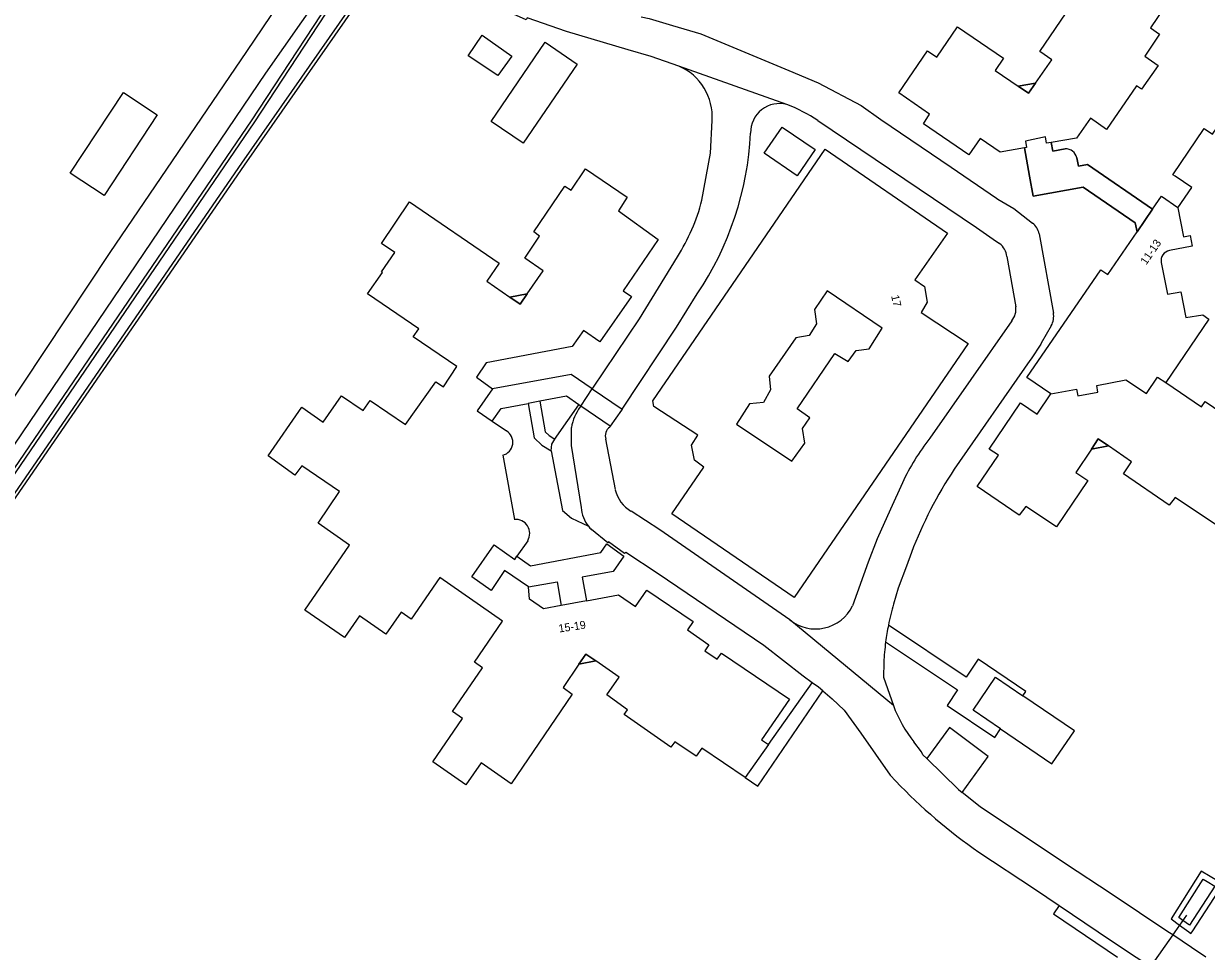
# Model space of a CAD drawing. Extents: x 158132 to 159658, y 385257 to 387209.
# Drawn here: x 159219.1 to 159366.9, y 385997.6 to 386113.4 of the extents above; entities that cross this region are included whole.
import ezdxf

# ---------------------------------------------------------------- set-up
doc = ezdxf.new("R2010")
doc.units = 0
for name, color, linetype in [('IMGEO_Duiker', 7, 'Continuous'), ('IMGEO_Groenvoorziening', 7, 'Continuous'), ('IMGEO_Pand', 7, 'Continuous'), ('IMGEO_Pand_nummerreeks', 7, 'Continuous'), ('IMGEO_Pand_overbouw', 7, 'Continuous'), ('IMGEO_Parkeervlak_open', 7, 'Continuous'), ('IMGEO_Rijbaan_lokaal_gesloten', 7, 'Continuous'), ('IMGEO_Voetpad_open', 7, 'Continuous'), ('IMGEO_Waterloop', 7, 'Continuous')]:
    doc.layers.add(name, color=color, linetype=linetype)

msp = doc.modelspace()

# ---------------------------------------------------------------- linework, layer by layer
at = {"layer": 'IMGEO_Duiker'}
msp.add_lwpolyline([(159364.38, 386002.06), (159363.53, 386000.84), (159362.95, 386000), (159362.67, 385999.6), (159359.91, 385995.65), (159358.31, 385993.36), (159357.26, 385991.85)], dxfattribs=at)
at = {"layer": 'IMGEO_Groenvoorziening'}
for points in [[(159211.05, 386044.02), (159246.68, 386095.71), (159262.72, 386118.74), (159262.51, 386120.37), (159261.9, 386120.78), (159261.17, 386121.26), (159260.05, 386120.35), (159247.53, 386101.26), (159209.27, 386045.25)], [(159343.38, 386105.59), (159345.53, 386105.96)], [(159358.22, 386087.41), (159357.99, 386088.53), (159351.47, 386092.96), (159345.24, 386091.86), (159344.79, 386094.36), (159344.16, 386097.89)], [(159347.5, 386098.55), (159347.68, 386097.45), (159349.25, 386097.78)], [(159350.69, 386096.64), (159350.88, 386095.61), (159352.04, 386095.79), (159360.15, 386090.24)], [(159279.83, 386079.26), (159282.02, 386079.67)], [(159354.64, 386060.67), (159352.51, 386060.27)], [(159290.58, 386033.81), (159288.48, 386033.4)], [(159368.96, 386005.93), (159367.34, 386006.89), (159366.22, 386007.55), (159362.48, 386001.6), (159363.53, 386000.84), (159364.68, 386000), (159364.95, 385999.8), (159365.08, 386000), (159368.96, 386005.93)]]:
    msp.add_lwpolyline(points, dxfattribs=at)
msp.add_arc((159349.27, 386096.33), 1.44, 12.0964, 91.081, dxfattribs=at)
at = {"layer": 'IMGEO_Pand'}
for points in [[(159345.53, 386105.96), (159347.56, 386108.88), (159346.06, 386109.9), (159349.99, 386115.64), (159350.99, 386114.96), (159355.38, 386121.31), (159358.06, 386119.48), (159358.15, 386119.59), (159359.43, 386118.64), (159359.56, 386118.8), (159362.52, 386116.78), (159359.88, 386112.88), (159361, 386112.06), (159359.19, 386109.35), (159360.84, 386108.18), (159358.78, 386105.2), (159358.15, 386105.62), (159354.39, 386100.18), (159352.38, 386101.59), (159350.66, 386099.08), (159347.5, 386098.55)], [(159344.16, 386097.89), (159341.12, 386097.34), (159338.63, 386099.05), (159337.2, 386097.02), (159331.52, 386100.9), (159332.29, 386102.07), (159328.43, 386104.75), (159332.03, 386109.98), (159333.19, 386109.21), (159335.8, 386113.01), (159341.54, 386109.07), (159340.47, 386107.55), (159343.38, 386105.59)], [(159278.36, 386106.9), (159274.62, 386109.39), (159276.38, 386111.95), (159280.1, 386109.33), (159278.36, 386106.9)], [(159277.51, 386101.19), (159284.25, 386111.07), (159288.26, 386108.34), (159281.52, 386098.46), (159277.51, 386101.19)], [(159345.53, 386105.96), (159344.67, 386104.72), (159343.38, 386105.59)], [(159363.33, 386090.38), (159365.05, 386092.93), (159362.96, 386094.34), (159362.7, 386094.52), (159366.6, 386100.31), (159367.66, 386099.59), (159371.3, 386104.98), (159375.09, 386102.42), (159375.76, 386103.43), (159376.87, 386102.67), (159378.1, 386104.47), (159381.25, 386102.35), (159377.56, 386096.85), (159378.57, 386096.17), (159374.68, 386090.38), (159373.18, 386091.39), (159371.26, 386088.52)], [(159231.56, 386104.78), (159235.78, 386101.99), (159229.16, 386091.95), (159224.93, 386094.74), (159231.56, 386104.78)], [(159311.64, 386097.21), (159313.88, 386100.48), (159317.99, 386097.66), (159315.76, 386094.39), (159311.64, 386097.21)], [(159347.5, 386098.55), (159346.9, 386098.45), (159346.76, 386099.24), (159344.29, 386098.71), (159344.42, 386097.94), (159344.16, 386097.89)], [(159304.07, 386058.01), (159302.92, 386058.89), (159302.53, 386060.76), (159303.35, 386062.02), (159297.85, 386065.6), (159297.72, 386066.29), (159319.25, 386097.72), (159334.52, 386087.24), (159330.43, 386081.4), (159331.64, 386080.57), (159332.01, 386078.61), (159331.22, 386077.34), (159337.1, 386073.46), (159315.37, 386041.72), (159300.08, 386052.17), (159304.07, 386058.01)], [(159282.02, 386079.67), (159283.99, 386082.54), (159281.73, 386084.09), (159283.56, 386086.86), (159282.83, 386087.4), (159286.72, 386093.11), (159287.51, 386092.58), (159289.32, 386095.28), (159294.51, 386091.71), (159293.41, 386090.03), (159298.38, 386086.42), (159294.02, 386080.05), (159295.04, 386079.34), (159291.09, 386073.68), (159289.05, 386075.07), (159287.64, 386073.08), (159276.87, 386071.04), (159275.67, 386069.23), (159277.67, 386067.81)], [(159360.15, 386090.24), (159361.26, 386091.86), (159363.32, 386090.45), (159363.33, 386090.38)], [(159288.48, 386033.4), (159286.49, 386030.49), (159287.63, 386029.66), (159280.03, 386018.47), (159276.27, 386021.08), (159274.35, 386018.34), (159270.24, 386021.21), (159273.95, 386026.65), (159272.7, 386027.51), (159276.43, 386032.95), (159275.41, 386033.66), (159278.92, 386038.79), (159271.08, 386044.23), (159267.53, 386039.05), (159266.25, 386039.9), (159264.34, 386037.17), (159261.06, 386039.43), (159259.19, 386036.73), (159254.23, 386040.15), (159259.83, 386048.27), (159255.89, 386051.04), (159258.56, 386054.96), (159253.85, 386058.19), (159253, 386057.03), (159249.67, 386059.42), (159253.84, 386065.52), (159256.54, 386063.64), (159258.81, 386066.94), (159261.51, 386065.09), (159262.39, 386066.32), (159266.82, 386063.33), (159270.59, 386068.68), (159271.54, 386068.04), (159273.23, 386070.6), (159267.78, 386074.27), (159268.46, 386075.27), (159262.08, 386079.66), (159263.93, 386082.3), (159263.83, 386082.4), (159265.46, 386084.81), (159263.79, 386085.92), (159267.32, 386091.16), (159278.51, 386083.48), (159276.96, 386081.24), (159279.83, 386079.26)], [(159360.15, 386090.24), (159358.22, 386087.41)], [(159363.33, 386090.38), (159364.03, 386086.77), (159364.83, 386086.93), (159365.08, 386085.59), (159362.26, 386085.06)], [(159347.45, 386067.15), (159344.46, 386069.2), (159353.67, 386082.67), (159354.56, 386082.06), (159358.22, 386087.41)], [(159361.24, 386083.56), (159362, 386079.6), (159363.67, 386079.92), (159364.3, 386076.69), (159366.42, 386077.03), (159367.19, 386076.5)], [(159319.51, 386080.03), (159317.92, 386077.68), (159318.15, 386075.9), (159317.24, 386074.44), (159315.56, 386074.17), (159312.23, 386069.39), (159312.42, 386067.65), (159311.55, 386066.1), (159309.77, 386065.9), (159308.16, 386063.39), (159315.06, 386058.75), (159316.71, 386061.02), (159316.42, 386062.85), (159317.32, 386064.16), (159315.75, 386065.3), (159320.46, 386072.2), (159322.13, 386071.19), (159323.13, 386072.6), (159324.73, 386072.79), (159326.38, 386075.35), (159319.51, 386080.03)], [(159282.02, 386079.67), (159281.13, 386078.37), (159279.83, 386079.26)], [(159367.19, 386076.5), (159361.79, 386068.57)], [(159347.45, 386067.15), (159350.65, 386067.76), (159350.82, 386066.93), (159353.33, 386067.39), (159353.17, 386068.21), (159356.81, 386068.93), (159359.38, 386067.23), (159360.76, 386069.27), (159361.79, 386068.57)], [(159361.79, 386068.57), (159366.27, 386065.55), (159366.71, 386066.22), (159369.72, 386064.16), (159368.6, 386062.46), (159371.29, 386060.57), (159370.51, 386059.44), (159374.35, 386056.76), (159372.36, 386053.78), (159372.22, 386053.88), (159371.28, 386052.58), (159371.17, 386052.65), (159369.38, 386049.95), (159362.99, 386054.24), (159362.24, 386053.27), (159356.52, 386057.16), (159357.54, 386058.69), (159354.64, 386060.67)], [(159277.67, 386067.81), (159275.78, 386065.03), (159277.63, 386063.76)], [(159352.51, 386060.27), (159350.55, 386057.34), (159352.05, 386056.33), (159348.13, 386050.57), (159344.31, 386053.12), (159343.5, 386052), (159338.23, 386055.58), (159340.9, 386059.52), (159339.73, 386060.28), (159343.67, 386066.03), (159345.73, 386064.62), (159347.45, 386067.15)], [(159277.63, 386063.76), (159279.42, 386062.54)], [(159352.51, 386060.27), (159353.37, 386061.54), (159354.64, 386060.67)], [(159278.96, 386059.5), (159280.41, 386051.49)], [(159282.08, 386048.83), (159280.74, 386046.88)], [(159282.16, 386043.08), (159279.19, 386045.1), (159277.51, 386042.61), (159275.11, 386044.3), (159277.89, 386048.33), (159280.47, 386046.49), (159280.74, 386046.88)], [(159286.27, 386040.73), (159284.07, 386040.32), (159282.32, 386041.52), (159282.16, 386043.08)], [(159289.43, 386041.33), (159286.27, 386040.73)], [(159289.43, 386041.33), (159293.44, 386042.08), (159295.55, 386040.63), (159296.96, 386042.66), (159302.74, 386038.75), (159302.05, 386037.7), (159304.73, 386035.83), (159304.21, 386035.09), (159305.76, 386034.03), (159306.3, 386034.79), (159314.77, 386029.04), (159311.3, 386023.98), (159312.18, 386023.39)], [(159288.48, 386033.4), (159289.35, 386034.67), (159290.58, 386033.81)], [(159309.25, 386019.25), (159303.84, 386022.94), (159303.11, 386021.91), (159300.48, 386023.72), (159299.98, 386023.05), (159294.11, 386027.11), (159294.56, 386027.73), (159291.98, 386029.58), (159293.49, 386031.79), (159290.58, 386033.81)], [(159341.17, 386025.33), (159337.72, 386027.68), (159340.54, 386031.8), (159343.95, 386029.47)], [(159341.17, 386025.33), (159347.58, 386020.96), (159350.4, 386025.07), (159343.95, 386029.47)], [(159312.18, 386023.39), (159309.25, 386019.25)]]:
    msp.add_lwpolyline(points, dxfattribs=at)
for centre, radius, start, end in [((159362.48, 386083.82), 1.26, 100.2132, 191.7914), ((159278.55, 386061.12), 1.67, 284.0563, 58.6242), ((159280.56, 386049.73), 1.77, 329.3209, 95.1105)]:
    msp.add_arc(centre, radius, start, end, dxfattribs=at)
at = {"layer": 'IMGEO_Pand_overbouw'}
for points in [[(159345.53, 386105.96), (159343.38, 386105.59), (159344.67, 386104.72)], [(159279.83, 386079.26), (159281.13, 386078.37), (159282.02, 386079.67)], [(159352.51, 386060.27), (159354.64, 386060.67), (159353.37, 386061.54)], [(159288.48, 386033.4), (159290.58, 386033.81), (159289.35, 386034.67), (159288.48, 386033.4)]]:
    msp.add_lwpolyline(points, close=True, dxfattribs=at)
for points in [[(159349.25, 386097.78), (159347.68, 386097.45), (159347.5, 386098.55), (159346.9, 386098.45), (159346.76, 386099.24), (159344.29, 386098.71), (159344.42, 386097.94), (159344.16, 386097.89), (159344.79, 386094.36), (159345.24, 386091.86), (159351.47, 386092.96), (159357.99, 386088.53), (159358.22, 386087.41), (159360.15, 386090.24), (159352.04, 386095.79)], [(159352.04, 386095.79), (159350.88, 386095.61), (159350.69, 386096.64)]]:
    msp.add_lwpolyline(points, dxfattribs=at)
msp.add_arc((159349.27, 386096.33), 1.44, 12.0964, 91.081, dxfattribs=at)
at = {"layer": 'IMGEO_Parkeervlak_open'}
for points in [[(159285.47, 386061.5), (159285.7, 386061.87), (159288.48, 386065.79)], [(159285.01, 386060.05), (159286.41, 386052.6), (159287.54, 386051.65), (159289.67, 386050.63)], [(159336.36, 386017.41), (159339.6, 386021.9), (159334.78, 386025.51), (159331.94, 386021.63)]]:
    msp.add_lwpolyline(points, dxfattribs=at)
at = {"layer": 'IMGEO_Rijbaan_lokaal_gesloten'}
for points in [[(159182.09, 386014.12), (159183.73, 386016.54), (159194.42, 386031.4), (159229.89, 386084.81), (159246.98, 386109.91), (159257.08, 386124.85)], [(159258.33, 386120.06), (159249.31, 386107.22), (159204.57, 386041.21), (159184.98, 386012.08), (159184.96, 386012.05)], [(159300.96, 386108.09), (159297.51, 386109.27), (159294.64, 386110.12), (159286.92, 386112.41), (159281.99, 386114.1), (159281.87, 386113.87), (159278.73, 386115.28), (159278.8, 386115.43), (159277.49, 386116.31), (159276.36, 386116.9), (159269.53, 386120.94)], [(159296.27, 386114.24), (159297.27, 386114.02), (159300.16, 386113.16), (159303.71, 386112.11), (159314.7, 386107.55), (159318.37, 386106), (159323.74, 386103.16), (159326.21, 386101.41), (159334.98, 386095.47), (159340.64, 386091.6), (159340.83, 386091.48), (159342.82, 386090.3), (159345.16, 386088.49)], [(159314.47, 386103.28), (159300.96, 386108.09)], [(159303.85, 386091.34), (159304.92, 386097.21), (159305.13, 386101.28)], [(159318.33, 386101.28), (159338.14, 386087.92), (159340.24, 386086.49), (159341.04, 386085.92)], [(159345.97, 386087.15), (159347.76, 386077.26)], [(159290.15, 386067.78), (159290.22, 386067.89), (159296.05, 386076.54), (159300.78, 386084.27)], [(159341.93, 386084.31), (159343.05, 386078.05)], [(159293.87, 386065.25), (159300.68, 386075.48), (159303.27, 386079.64)], [(159342.55, 386076.3), (159332.33, 386061.62)], [(159347.5, 386075.67), (159346.23, 386073.49), (159346.18, 386073.39), (159344.97, 386071.54), (159344.83, 386071.35), (159335.38, 386057.77)], [(159288.71, 386065.63), (159290.15, 386067.78)], [(159290.15, 386067.78), (159293.87, 386065.25)], [(159288.64, 386065.53), (159288.71, 386065.63)], [(159292.4, 386063.12), (159288.71, 386065.63)], [(159293.87, 386065.25), (159293.79, 386065.14), (159292.4, 386063.12)], [(159288.78, 386052.98), (159287.56, 386060.73), (159287.53, 386062.97)], [(159292.32, 386063.02), (159292.4, 386063.12)], [(159293.03, 386055.21), (159291.84, 386061.5)], [(159328.9, 386056.06), (159327.4, 386052.75), (159325.76, 386049.08), (159324.6, 386046.17), (159322.67, 386040.68)], [(159314.83, 386038.94), (159298.58, 386050.18), (159294.99, 386052.52)], [(159317.63, 386031.1), (159316.51, 386031.9), (159311.58, 386035.75), (159298.36, 386044.7), (159294.33, 386047.36), (159294.19, 386047.22), (159292.17, 386048.69), (159292.11, 386048.58), (159290.06, 386050.21)], [(159330.04, 386047.37), (159329.4, 386045.64), (159328.38, 386042.89), (159327.79, 386040.9)], [(159327.77, 386028.26), (159314.83, 386038.94)], [(159326.57, 386033.62), (159326.52, 386031.8), (159327.77, 386028.26)], [(159318.95, 386030.1), (159318.43, 386030.54), (159317.63, 386031.1)], [(159318.95, 386030.1), (159320.14, 386029.09), (159321.62, 386027.66), (159323.69, 386024.8), (159327.35, 386019.57), (159328.06, 386018.79)], [(159331.94, 386021.63), (159331.46, 386022.11), (159331.27, 386022.46), (159330.33, 386023.7)], [(159331.94, 386021.63), (159335.91, 386017.76), (159336.36, 386017.41)], [(159366.81, 385996.83), (159365.02, 385998.03), (159365, 385998.05), (159362.67, 385999.6), (159362.07, 386000), (159354.98, 386004.72), (159349.29, 386008.47), (159338.61, 386015.61), (159336.36, 386017.41)], [(159338.45, 386009.93), (159345.38, 386005.36), (159348.48, 386003.28)], [(159348.48, 386003.28), (159353.37, 386000), (159357.27, 385997.38), (159359.91, 385995.65), (159362.06, 385994.25), (159362.35, 385994.06), (159363.93, 385993.02)]]:
    msp.add_lwpolyline(points, dxfattribs=at)
for centre, radius, start, end in [((159298.22, 386101.73), 6.92, 356.2434, 66.664), ((159313.52, 386099.82), 3.59, 74.6472, 181.3944), ((159308.31, 386086.58), 17.8, 55.6991, 69.7327), ((159270.35, 386101.72), 39.63, 326.1427, 357.1243), ((159279.05, 386097.91), 25.66, 327.8886, 345.1676), ((159343.93, 386086.83), 2.06, 8.7647, 53.5626), ((159339.73, 386084.14), 2.21, 4.4468, 53.6926), ((159340.96, 386077.7), 2.12, 318.7172, 9.5991), ((159345.52, 386076.81), 2.28, 330.159, 11.5367), ((159293.6, 386061.86), 6.17, 143.5055, 169.6334), ((159293.12, 386061.93), 1.35, 126.2293, 198.6545), ((159353.6, 386044.66), 27.2, 141.4288, 155.2241), ((159378.27, 386029.15), 51.56, 146.2907, 159.3077), ((159297.1, 386056.12), 4.18, 192.6758, 239.5387), ((159292.79, 386053.15), 4.02, 182.547, 218.918), ((159292.73, 386053.09), 3.93, 218.819, 227.2504), ((159318.04, 386042.98), 5.17, 231.5281, 333.5898), ((159358.35, 386032.1), 31.81, 163.9268, 168.7575), ((159358.94, 386031.93), 32.42, 168.6757, 172.4351), ((159359.21, 386031.92), 32.69, 172.4767, 177.0142), ((159342.69, 386033.65), 15.86, 199.8565, 218.834), ((159378.7, 386067.59), 70.32, 223.9382, 235.0831)]:
    msp.add_arc(centre, radius, start, end, dxfattribs=at)
at = {"layer": 'IMGEO_Voetpad_open'}
for points in [[(159290.15, 386067.78), (159287.5, 386069.59), (159277.67, 386067.81)], [(159288.48, 386065.79), (159286.91, 386066.86), (159283.6, 386066.24)], [(159277.63, 386063.76), (159278.77, 386065.34), (159282.14, 386065.97)], [(159283.6, 386066.24), (159282.14, 386065.97)], [(159282.14, 386065.97), (159282.88, 386061.69), (159283.83, 386060.77), (159285.01, 386060.05)], [(159283.6, 386066.24), (159284.26, 386062.42), (159284.74, 386061.95), (159285.47, 386061.5)], [(159288.71, 386065.63), (159288.48, 386065.79)], [(159285.01, 386060.05), (159285.09, 386060.88), (159285.47, 386061.5)], [(159280.74, 386046.88), (159282.42, 386045.71), (159291.21, 386047.37), (159291.95, 386048.45), (159294.08, 386046.91), (159292.76, 386044.99), (159288.89, 386044.29), (159289.43, 386041.33)], [(159282.16, 386043.08), (159285.77, 386043.7), (159286.27, 386040.73)], [(159343.95, 386029.47), (159344.32, 386030.02), (159338.35, 386034.02), (159336.86, 386031.79), (159327.15, 386038.3)], [(159326.8, 386036.2), (159335.78, 386030.19), (159334.49, 386028.26), (159340.46, 386024.26), (159341.17, 386025.33)], [(159312.18, 386023.39), (159317.63, 386031.1)], [(159309.25, 386019.25), (159310.82, 386018.18), (159318.95, 386030.1)], [(159348.48, 386003.28), (159347.79, 386002.25), (159355.76, 385996.83)]]:
    msp.add_lwpolyline(points, dxfattribs=at)
at = {"layer": 'IMGEO_Waterloop'}
for points in [[(159211.07, 386044.81), (159210.01, 386045.54), (159247.89, 386101.02), (159260.38, 386120.05), (159261.2, 386120.71), (159261.64, 386120.42), (159262.1, 386120.12), (159262.26, 386118.85), (159246.32, 386095.96), (159211.07, 386044.81)], [(159364.76, 386000.83), (159363.94, 386001.42), (159363.45, 386001.79), (159366.46, 386006.58), (159366.98, 386006.27), (159367.95, 386005.7), (159364.76, 386000.83)]]:
    msp.add_lwpolyline(points, dxfattribs=at)

# ---------------------------------------------------------------- texts
at = {"layer": 'IMGEO_Pand_nummerreeks'}
for s, rotation, p in [('11-13', 55.5311, (159359.36, 386083.2)), ('17', 282.7008, (159327.48, 386079.4)), ('15-19', 8.5351, (159286.01, 386037.36))]:
    msp.add_text(s, height=1, rotation=rotation, dxfattribs=at).set_placement(p)

doc.saveas('drawing.dxf')
